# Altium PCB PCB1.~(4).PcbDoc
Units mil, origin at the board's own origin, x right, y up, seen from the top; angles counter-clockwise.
Board outline 6000 x 4000 mil, 2 copper layers (Top Layer, Bottom Layer); 23 components, 29 nets, 103 pads, 0 vias.
Unrouted connection lines stored in the file: 63.
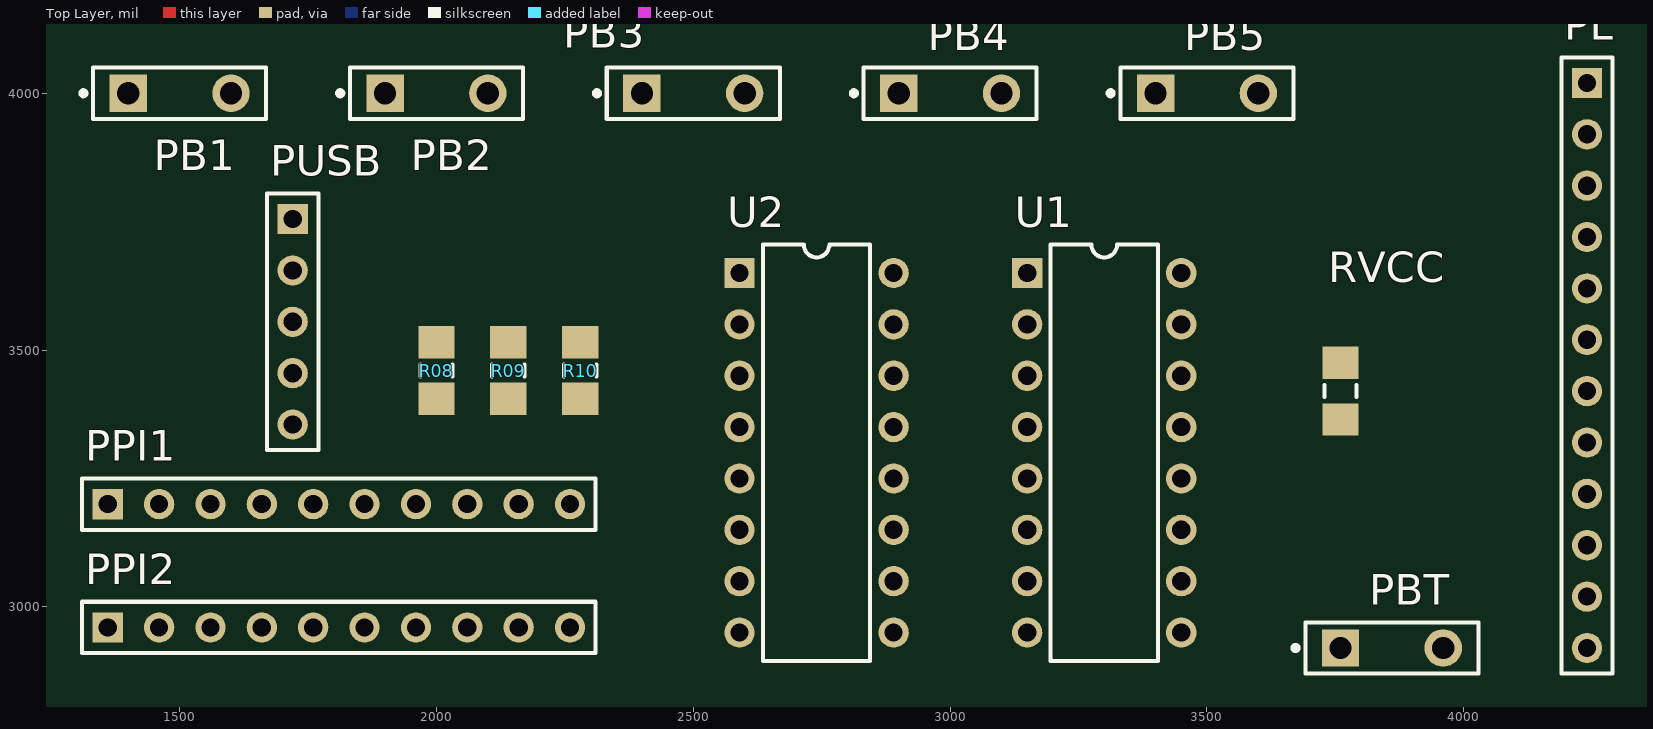
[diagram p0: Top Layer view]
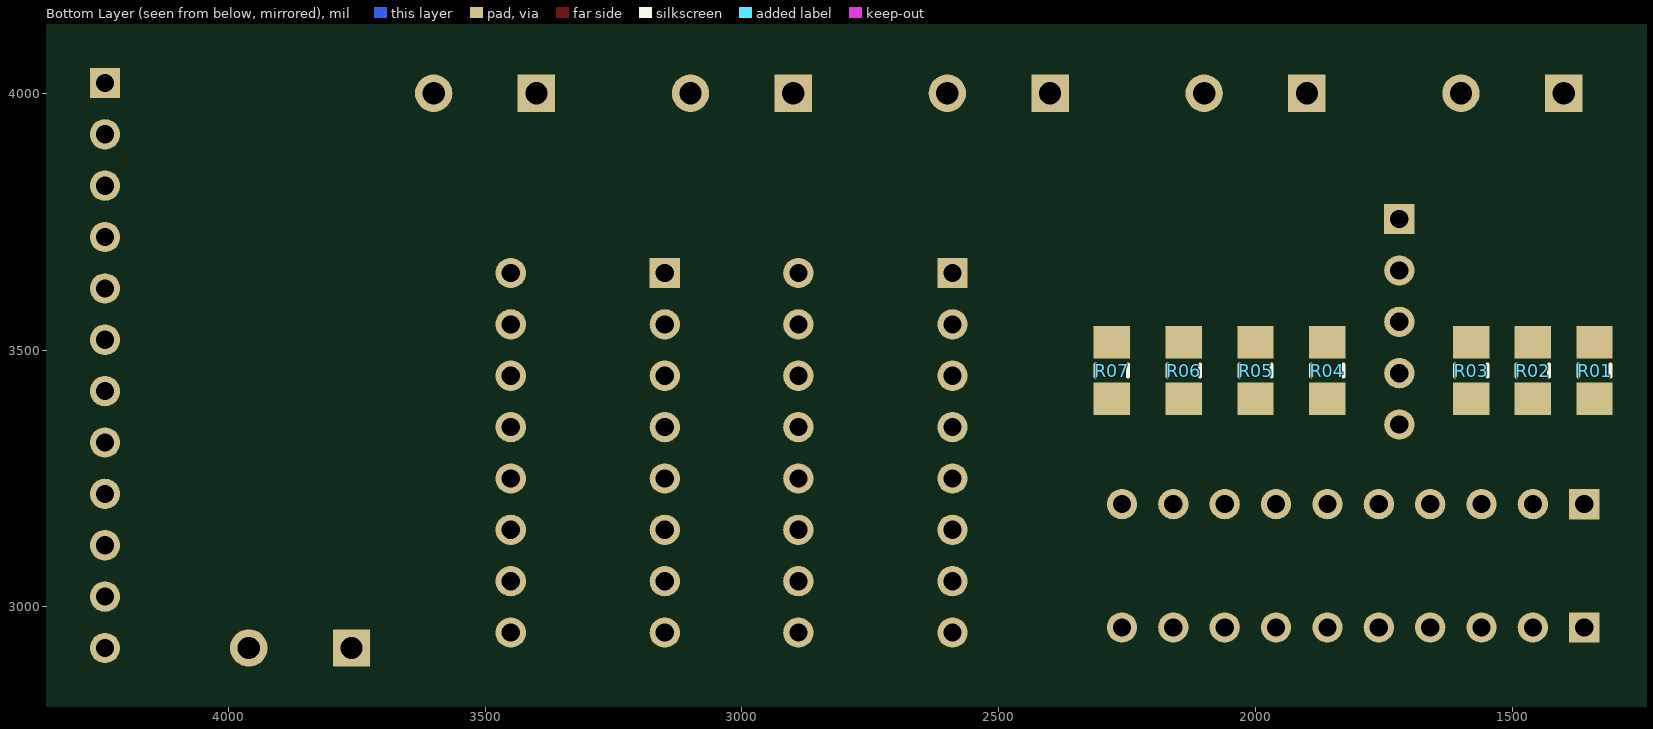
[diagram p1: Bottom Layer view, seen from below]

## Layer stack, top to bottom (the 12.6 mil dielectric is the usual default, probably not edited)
Top Layer: signal copper 1.4
Dielectric: dielectric 12.6, FR-4, Dk 4.8
Bottom Layer: signal copper 1.4

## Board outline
1000,1000 7000,1000 7000,5000 1000,5000

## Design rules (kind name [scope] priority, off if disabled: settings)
Clearance [All] p1: gap=10
ComponentClearance [All] p1: gap=10 collisioncheckmode=3 verticalgap=10
PolygonConnect [All] p1: connectstyle=Relief reliefconductorwidth=10 reliefentries=4 polygonreliefangle="90 Angle"
RoomDefinition Sheet1 [InComponentClass('Sheet1')] p1: confinementstyle=ConfineIn formatcopy=TRUE lockcomponents=FALSE outline 7045,960 7300,960 7300,1580 7045,1580
RoutingVias [All] p1: holewidth=28 width=50 viastyle="Through Hole" minholewidth=28 minwidth=50 maxholewidth=28 maxwidth=50
SolderMaskExpansion [All] p1: expansion=4
TestPointUsage [All] p1: valid=0 allowmultiple=FALSE
Testpoint [All] p1: side=15 testpointundercomponent=TRUE minsize=40 maxsize=100 preferedsize=60 minholesize=0 maxholesize=40 preferedholesize=32 testpointgrid=1 style=1023 order=0123456789
Width Width_2 [All] p1: maxlimit=30 minlimit=15 preferedwidth=20
Width Width_1 [InNet('VCC')] p2: maxlimit=30 minlimit=20 preferedwidth=30
Width [InNet('GND')] p3: maxlimit=30 minlimit=20 preferedwidth=30
18 further rules are at their usual default settings.

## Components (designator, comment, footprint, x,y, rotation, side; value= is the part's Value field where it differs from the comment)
PB1 "Header 2" SPST-2 1500,4000 r0 top
PB2 "Header 2" SPST-2 2000,4000 r0 top
PB3 "Header 2" SPST-2 2500,4000 r0 top
PB4 "Header 2" SPST-2 3000,4000 r0 top
PB5 "Header 2" SPST-2 3500,4000 r0 top
PBT "Header 2" SPST-2 3860,2920 r0 top
PL "Header 12" HDR1X12 4240,4020 r270 top
PPI1 "Header 10" HDR1X10 1360,3200 r0 top
PPI2 "Header 10" HDR1X10 1360,2960 r0 top
PUSB "Header 5" HDR1X5 1720,3755 r270 top
R01 "Res1" 3216[1206] 1340,3460 r90 bottom
R02 "Res1" 3216[1206] 1460,3460 r90 bottom
R03 "Res1" 3216[1206] 1580,3460 r90 bottom
R04 "Res1" 3216[1206] 1860,3460 r270 bottom
R05 "Res1" 3216[1206] 2000,3460 r270 bottom
R06 "Res1" 3216[1206] 2140,3460 r270 bottom
R07 "Res1" 3216[1206] 2280,3460 r90 bottom
R08 "Res1" 3216[1206] 2000,3460 r90 top
R09 "Res1" 3216[1206] 2140,3460 r90 top
R10 "Res1" 3216[1206] 2280,3460 r270 top
RVCC "Res1" 3216[1206] 3760,3420 r90 top
U1 "SN74HC138D" DIP-16 3300,3300 r270 top
U2 "SN74HC138D" DIP-16 2740,3300 r270 top

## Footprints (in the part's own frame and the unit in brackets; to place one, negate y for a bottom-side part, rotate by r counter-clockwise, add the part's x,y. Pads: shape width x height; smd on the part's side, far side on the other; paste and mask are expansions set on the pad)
3216[1206] [mm] "Chip Resistor; Body 3.2 x 1.6 mm (LxW typ)"
  rect 1.6x1.8 smd: 1(-1.4,0) 2(1.4,0)
  silkscreen extent -0.3,-0.8 0.3,0.8
DIP-16 [mm] "DIP; 16 Leads; Row Spacing 7.62 mm; Pitch 2.54 mm"
  rect 1.5x1.5 hole 0.9: 1(-8.89,-3.81)
  round 1.5 hole 0.9: 2(-6.35,-3.81) 3(-3.81,-3.81) 4(-1.27,-3.81) 5(1.27,-3.81) 6(3.81,-3.81) 7(6.35,-3.81) 8(8.89,-3.81) 9(8.89,3.81) 10(6.35,3.81) 11(3.81,3.81) 12(1.27,3.81) 13(-1.27,3.81) 14(-3.81,3.81) 15(-6.35,3.81) 16(-8.89,3.81)
  silkscreen extent -10.3,-2.65 10.3,2.65
HDR1X5 [mm] "Connector; Header; 5 Position"
  rect 1.5x1.5 hole 0.9: 1(0,0)
  round 1.5 hole 0.9: 2(2.54,0) 3(5.08,0) 4(7.62,0) 5(10.16,0)
  silkscreen extent -1.27,-1.27 11.43,1.27
HDR1X10 [mm] "Connector; Header; 10 Position"
  rect 1.5x1.5 hole 0.9: 1(0,0)
  round 1.5 hole 0.9: 2(2.54,0) 3(5.08,0) 4(7.62,0) 5(10.16,0) 6(12.7,0) 7(15.24,0) 8(17.78,0) 9(20.32,0) 10(22.86,0)
  silkscreen extent -1.27,-1.27 24.13,1.27
HDR1X12 [mm] "Connector; Header; 12 Position"
  rect 1.5x1.5 hole 0.9: 1(0,0)
  round 1.5 hole 0.9: 2(2.54,0) 3(5.08,0) 4(7.62,0) 5(10.16,0) 6(12.7,0) 7(15.24,0) 8(17.78,0) 9(20.32,0) 10(22.86,0) 11(25.4,0) 12(27.94,0)
  silkscreen extent -1.27,-1.27 29.21,1.27
SPST-2 [mm] "Circuit Breaker; 2 Leads"
  rect 1.85x1.85 hole 1.1: 1(-2.54,0)
  round 1.85 hole 1.1: 2(2.54,0)
  silkscreen extent -4.89,-1.27 4.28,1.27

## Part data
PB1 PB2 PB3 PB4 PB5 PBT: "Header, 2-Pin"
PL: "Header, 12-Pin"
PPI1 PPI2: "Header, 10-Pin"
PUSB: "Header, 5-Pin"
R01 R02 R03 R04 R05 R06 R07 R08 R09 R10 RVCC: "Resistor"
U1 U2: "3-Line to 8-Line Decoder / Demultiplexer"

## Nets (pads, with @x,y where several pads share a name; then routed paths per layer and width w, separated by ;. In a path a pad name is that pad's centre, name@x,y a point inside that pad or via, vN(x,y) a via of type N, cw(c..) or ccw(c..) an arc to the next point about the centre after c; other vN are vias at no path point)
GND: PBT.2 PL.12 PPI2.10 PUSB.5 R01.1 R02.1 R03.1 R04.1 R05.1 R06.1 R07.1 R08.1 R09.1 R10.1 U1.4 U1.5 U1.8 U2.4 U2.5 U2.8
NetPB1_1: PB1.1 PPI1.1 R01.2
NetPB1_2: PB1.2 PPI1.2 R02.2
NetPB2_1: PB2.1 PPI1.3 R03.2
NetPB2_2: PB2.2 PPI1.4 R04.2
NetPB3_1: PB3.1 PPI1.5 R05.2
NetPB3_2: PB3.2 PPI1.6 R06.2
NetPB4_1: PB4.1 PPI1.7 R07.2
NetPB4_2: PB4.2 PPI1.8 R08.2
NetPB5_1: PB5.1 PPI1.9 R09.2
NetPB5_2: PB5.2 PPI1.10 R10.2
NetPBT_1: PBT.1 RVCC.1
NetPL_1: PL.1 U1.15
NetPL_2: PL.2 U1.14
NetPL_3: PL.3 U1.13
NetPL_4: PL.4 U1.12
NetPL_5: PL.5 U1.11
NetPL_6: PL.6 U1.10
NetPL_7: PL.7 U1.9
NetPL_8: PL.8 U1.7
NetPL_9: PL.9 U2.15
NetPL_10: PL.10 U2.14
NetPPI2_1: PPI2.1 U1.1 U2.1
NetPPI2_2: PPI2.2 U1.2 U2.2
NetPPI2_3: PPI2.3 U1.3 U2.3
NetPPI2_4: PPI2.4 U1.6
NetPPI2_5: PPI2.5 U2.6
NetPPI2_7: PPI2.7 RVCC.2
VCC: PL.11 PPI2.9 PUSB.1 U1.16 U2.16
pads on no net: PPI2.6 PPI2.8 PUSB.2 PUSB.3 PUSB.4 U2.7 U2.9 U2.10 U2.11 U2.12 U2.13

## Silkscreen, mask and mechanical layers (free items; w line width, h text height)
Mechanical 1:
  lines w10: 1270,2800 1270,4105 1275,4110 4355,4110 4375,4090 4375,2810 4385,2800 1270,2800 ; 1300,1010 3190,1010 3190,2800 1300,2800 1300,1010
